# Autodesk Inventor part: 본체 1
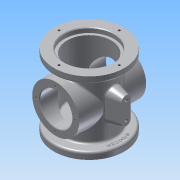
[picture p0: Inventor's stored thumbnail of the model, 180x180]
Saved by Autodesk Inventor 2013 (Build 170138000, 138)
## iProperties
Created: 2018-02
Part Number: 본체 1
Material: 알루미늄 6061
Document SubType Name: Modeling
Designer: Administrator
Density: 2.71 g/cm^3
Mass: 743.259 g
Surface Area: 827.643 cm^2
Volume: 274.265 cm^3
Author: Administrator
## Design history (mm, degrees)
sketch "스케치1"
  geometry: C1 r 37 at (0, 0); 1 further point
  constraints: 1 centre point, 1 coincident
  dimensions: "d0" = 74 diameter of C1
extrude "돌출1" new body sketch "스케치1" stored distance "d1" = 108; taper "d2" = 0 deg
sketch "스케치2"
  geometry: C1 r 37 at (0, 0) reference; C2 r 52.5 at (0, 0)
  constraints: 1 centre point, 1 coincident
  dimensions: "d3" = 105 diameter of C2
extrude "돌출2" join sketch "스케치2" distance "d4" = 10; taper "d5" = 0 deg
node "작업 평면1"
sketch "스케치3"
  geometry: C1 r 35 at (0, 0); 1 further point
  constraints: 1 centre point, 1 coincident
  dimensions: "d7" = 70 diameter of C1
extrude "돌출3" join sketch "스케치3" stored distance "d8" = 10; taper "d9" = 0 deg
sketch "스케치4"
  geometry: C1 r 52.5 at (0, 0) reference; C2 r 33 at (0, 0)
  constraints: 1 centre point, 1 coincident
  dimensions: "d10" = 66 diameter of C2
extrude "돌출4" cut sketch "스케치4" distance "d11" = 86; taper "d12" = 0 deg
sketch "스케치5"
  geometry: C1 r 33 at (0, 0) reference; C2 r 52.5 at (0, 0) reference; C3 r 37 at (0, 0)
  constraints: 1 centre point, 1 coincident
  dimensions: "d13" = 74 diameter of C3
extrude "돌출5" cut sketch "스케치5" distance "d14" = 7; taper "d15" = 0 deg
sketch "스케치6"
  geometry: C1 r 52.5 at (0, 0) reference; C2 r 34 at (0, 0)
  constraints: 1 centre point, 1 coincident
  dimensions: "d16" = 68 diameter of C2
extrude "돌출6" cut sketch "스케치6" distance "d17" = 16; taper "d18" = 0 deg
sketch "스케치7"
  geometry: C1 r 35 at (0, 0) reference; C2 r 24 at (0, 0)
  constraints: 1 centre point, 1 coincident
  dimensions: "d19" = 48 diameter of C2
extrude "돌출7" cut sketch "스케치7" stored distance "d20" = 16; taper "d21" = 0 deg
sketch "스케치8"
  geometry: C1 r 24 at (0, 0) reference; 1 further point
  constraints: 1 vertical alignment
  dimensions: "d22" = 29 distance of C1.centre point (0, 29)
hole "구멍1" sketch "스케치8" at (0, 29) diameter "d23" = 3.242; stored, may be unused: countersink angle "d27" = 90 deg, drill point angle "d29" = 118 deg; dims "d24" = 4, "d25" = 4, "d26" = 2, "d28" = 6
sketch "스케치9"
  geometry: C1 r 37 at (0, 0) reference; 1 further point
  constraints: 1 vertical alignment
  dimensions: "d33" = 45 distance of C1.centre point (0, 45)
hole "구멍2" sketch "스케치9" at (0, 45) diameter "d34" = 3.242; stored, may be unused: countersink angle "d38" = 90 deg, drill point angle "d40" = 118 deg; dims "d35" = 4, "d36" = 4, "d37" = 2, "d39" = 6
node "작업 평면2"
sketch "스케치11"
  geometry: L1 (7, 13)-(7, -13); L2 (-7, 13)-(-7, -13); A1 r 7 centre (0, 13) between (7, 13) and (-7, 13); A2 r 7 centre (0, -13) between (-7, -13) and (7, -13); 2 further points
  constraints: 4 end point, 4 point on circle, 3 tangent, 2 centre point, 2 vertical alignment, 1 horizontal alignment, 1 midpoint, 1 parallel
  dimensions: "d54" = 14 diameter of A1; "d56" = 14 diameter of A2; "d97" = 40 dimension on A2 A1
extrude "돌출8" join sketch "스케치11" stored distance "d58" = 16; taper "d59" = 15 deg
sketch "스케치13"
  geometry: C1 r 34 at (0, 0) reference; C2 r 5 at (0, 0)
  constraints: 1 centre point, 1 coincident
  dimensions: "d69" = 10 diameter of C2
extrude "돌출9" cut sketch "스케치13" distance "d70" = 16; taper "d71" = 0 deg
fillet "모깎기2" dims "d72" = 3
sketch "스케치14"
  geometry: C1 r 49.5 at (0, 0) reference; C2 r 43 at (0, 0)
  constraints: 1 centre point, 1 coincident, 1 other
  dimensions: "d73" = 86 diameter of C2
feature "엠보싱1" sketch "스케치14" dims "d74" = 0.5, "d75" = 0
fillet "모깎기6" dims "d79" = 3
fillet "모깎기7" dims "d80" = 3
fillet "모깎기8" dims "d81" = 3
chamfer "모따기1" distance "d82" = 1; stored, may be unused: second distance "d83" = 2, angle "d84" = 45 deg
chamfer "모따기2" distance "d85" = 1; stored, may be unused: second distance "d86" = 2, angle "d87" = 45 deg
fillet "모깎기9" dims "d88" = 3
fillet "모깎기10" dims "d89" = 3
sketch "스케치15"
  geometry: A1 r 7 centre (-13, 0) between (-13, 7) and (-13, -7) reference; A2 r 7 centre (13, 0) between (13, -7) and (13, 7) reference; 3 further points
  constraints: 2 coincident
hole "구멍4" sketch "스케치15" at (-13, 0), (13, 0) diameter "d90" = 4.134; stored, may be unused: countersink angle "d94" = 90 deg, drill point angle "d96" = 118 deg; dims "d91" = 6, "d92" = 4, "d93" = 2, "d95" = 8
chamfer "모따기3" distance "d98" = 1; stored, may be unused: second distance "d99" = 2, angle "d100" = 45 deg
fillet "모깎기11" dims "d101" = 3
node "솔리드1"
mirror "대칭1"
mirror "대칭2"
pattern_circular "원형 패턴1" dims angle "d31" = 360 deg
pattern_circular "원형 패턴2" dims angle "d42" = 360 deg
mirror "대칭3"
other parameters: "d52" = 55
